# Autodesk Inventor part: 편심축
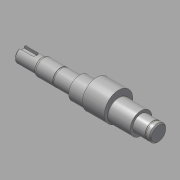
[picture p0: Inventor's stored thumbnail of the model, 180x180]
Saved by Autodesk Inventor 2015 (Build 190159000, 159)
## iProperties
Created: 2015-12
Part Number: 편심축
Material: 강철, 연강
Document SubType Name: Modeling
Designer: mduedu
Density: 7.86 g/cm^3
Appearance: 강철
Author: mduedu
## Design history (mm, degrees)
sketch "스케치1"
  geometry: L1 (-62.5, 0)-(62.5, 0); L2 (-62.5, 0)-(-62.5, 6.5); L3 (-62.5, 6.5)-(-43.5, 6.5); L4 (-43.5, 7)-(-42.634, 7.5); L5 (-42.634, 7.5)-(-9.5, 7.5); L6 (-9.5, 7.5)-(-9.5, 10); L7 (-9.5, 10)-(46.5, 10); L8 (46.5, 10)-(46.5, 7.5); L9 (46.5, 7.5)-(62.5, 7.5); L10 (62.5, 7.5)-(62.5, 0); L11 (-43.5, 6.5)-(-43.5, 7); 2 further points
  constraints: 22 end point, 6 parallel, 2 perpendicular, 1 coincident, 1 horizontal, 1 midpoint, 1 vertical
  dimensions: "d0" = 13 diameter of L3 L1; "d2" = 15 diameter of L5 L1; "d3" = 20 diameter of L7 L1; "d5" = 15 diameter of L9 L1; "d6" = 125 distance of L1.start L1.end; "d7" = 19 distance of L2.end L3.end; "d8" = 34 distance from line of L6 L3.end; "d9" = 56 distance of L6.end L7.end; "d41" = 14 diameter of L4.start L1; "d42" = 30 deg angle of L4 L3
revolve "회전1" sketch "스케치1" stored, may be unused: angle "d11" = 90 deg
node "작업 평면1"
sketch "스케치2"
  geometry: C1 r 13 at (0, 3); 1 further point
  constraints: 1 centre point, 1 vertical alignment
  dimensions: "d13" = 26 diameter of C1; "d14" = 3 distance of point (0, 0) C1.centre
extrude "돌출1" join sketch "스케치2" distance "d15" = 20; taper "d16" = 0 deg
node "작업 평면2"
sketch "스케치3"
  geometry: L1 (9.5, -2.5)-(-2.5, -2.5); L2 (-2.5, 2.5)-(9.5, 2.5); L3 (9.5, 2.5)-(9.5, -2.5); L4 (9.5, 6.5)-(9.5, -6.5) reference; A1 r 2.5 centre (-2.5, 0) between (-2.5, 2.5) and (-2.5, -2.5); 1 further point
  constraints: 6 end point, 2 point on circle, 2 tangent, 1 centre point, 1 collinear, 1 horizontal, 1 horizontal alignment, 1 parallel
  dimensions: "d17" = 5 distance of L2.end L1.start; "d19" = 12 distance from line of A1.centre L3
extrude "돌출2" cut sketch "스케치3" distance "d20" = 3; taper "d21" = 0 deg
chamfer "모따기1" distance "d22" = 1; stored, may be unused: second distance "d23" = 2, angle "d24" = 45 deg
fillet "모깎기1" dims "d25" = 3
sketch "스케치4"
  geometry: L1 (-9.5, -10)-(-9.5, 10) reference; L2 (-9.5, 0)-(0, 0); L3 (-26.65, 12.15)-(-25.5, 12.15); L4 (-25.5, 12.15)-(-25.5, 7.15); L5 (-25.5, 7.15)-(-26.65, 7.15); L6 (-26.65, 7.15)-(-26.65, 12.15); L7 (57.5, 12.15)-(58.65, 12.15); L8 (58.65, 12.15)-(58.65, 7.15); L9 (58.65, 7.15)-(57.5, 7.15); L10 (57.5, 7.15)-(57.5, 12.15); L11 (62.5, -7.5)-(62.5, 7.5) reference
  constraints: 18 end point, 4 parallel, 2 horizontal, 2 perpendicular, 1 midpoint
  dimensions: "d26" = 16 distance between parallel lines of L4 L1; "d27" = 1.15 distance of L3.start L3.end; "d28" = 14.3 diameter of L5 L2; "d29" = 5 distance of L3.end L4.end; "d30" = 1.15 distance of L7.start L7.end; "d31" = 5 distance of L7.end L8.end; "d32" = 5 distance between parallel lines of L10 L11; "d33" = 14.3 diameter of L9 L2
revolve "회전2" sketch "스케치4" stored, may be unused: angle "d34" = 90 deg
chamfer "모따기2" distance "d35" = 1; stored, may be unused: second distance "d36" = 2, angle "d37" = 45 deg
fillet "모깎기2" dims "d38" = 0.3
sketch "스케치5"
  geometry: 2 further points
  constraints: 1 coincident
sketch "스케치6"
  geometry: 1 further point
hole "구멍1" sketch "스케치6" at (2.5, -3.5) diameter "d43" = 4.917; stored, may be unused: countersink angle "d47" = 90 deg, drill point angle "d49" = 120 deg; dims "d44" = 14, "d45" = 4, "d46" = 2, "d48" = 17
node "솔리드1"
other parameters: "d12" = -15.5
